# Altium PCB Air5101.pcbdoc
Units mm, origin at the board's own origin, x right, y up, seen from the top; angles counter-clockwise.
Board outline 69.1 x 28.3 mm, 2 copper layers (Top Layer, Bottom Layer); 1 components, 0 nets, 10 pads, 0 vias.
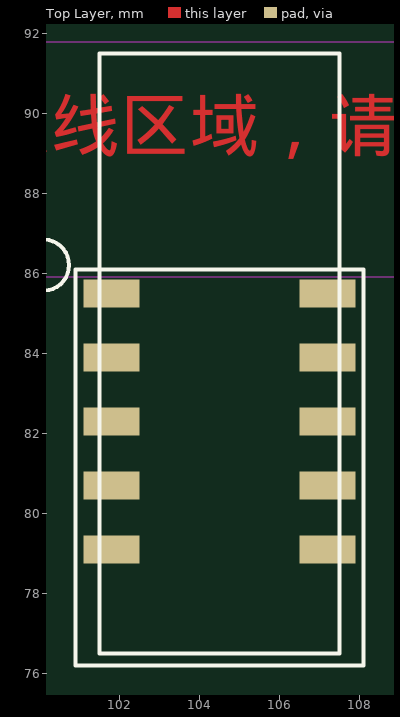
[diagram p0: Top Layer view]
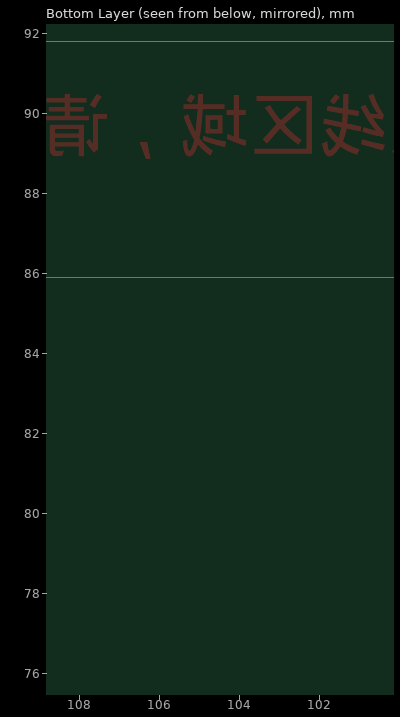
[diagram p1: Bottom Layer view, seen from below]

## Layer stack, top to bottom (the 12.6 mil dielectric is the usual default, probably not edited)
Top Layer: signal copper (thickness not stored)
Dielectric: dielectric 0.32, FR-4, Dk 4.8
Bottom Layer: signal copper (thickness not stored)

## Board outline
138.95,69.85 69.85,69.85 69.85,98.15 138.95,98.15

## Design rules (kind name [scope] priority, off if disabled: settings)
BoardOutlineClearance safeClearance [All] p0: genericclearance=0.254 ignorepadtopadclearanceinfootprint=FALSE except(0: Arc-SplitContinuation Track-SplitContinuation SMDPad-SplitContinuation THPad-SplitContinuation Via-SplitContinuation Fill-SplitContinuation Poly-SplitContinuation Region-SplitContinuation Text-SplitContinuation; 0.152: Track-CutoutEdge SMDPad-CutoutEdge THPad-CutoutEdge Via-CutoutEdge Fill-CutoutEdge Region-CutoutEdge; 0.3: Track-OutlineEdge SMDPad-OutlineEdge THPad-OutlineEdge Via-OutlineEdge Fill-OutlineEdge Region-OutlineEdge Poly-OutlineEdge Text-OutlineEdge)
Clearance safeClearance [All] p1: gap=0.178 ignorepadtopadclearanceinfootprint=FALSE except(0.152: Track-Track Track-SMDPad SMDPad-SMDPad Track-THPad SMDPad-THPad THPad-THPad Track-Via SMDPad-Via THPad-Via Via-Via Track-Fill SMDPad-Fill THPad-Fill Via-Fill Fill-Fill Track-Region SMDPad-Region THPad-Region Via-Region Fill-Region Region-Region Track-Poly SMDPad-Poly THPad-Poly Via-Poly Fill-Poly Region-Poly Poly-Poly Track-Text SMDPad-Text THPad-Text Via-Text Fill-Text Region-Text Poly-Text Text-Text; 0.175: Track-Hole SMDPad-Hole THPad-Hole Via-Hole Fill-Hole Region-Hole Poly-Hole Text-Hole Sheet-Hole; 0.3: Track-Sheet SMDPad-Sheet THPad-Sheet Via-Sheet Fill-Sheet Region-Sheet Poly-Sheet Text-Sheet)
DiffPairsRouting differentialPair [All] p1: maxuncoupledlength=10 minlimit=6 maxlimit=6 mostfreqgap=6 toplayer_minwidth=5 toplayer_prefwidth=10 toplayer_maxwidth=100 bottomlayer_minwidth=5 bottomlayer_prefwidth=10 bottomlayer_maxwidth=100
PasteMaskExpansion pasteMaskExpansion [All] p1: expansion=0
PlaneConnect innerPlane [All] p1: planeconnectstyle=Relief reliefexpansion=0.508 reliefentries=4 reliefconductorwidth=0.254 reliefairgap=0.254
PolygonConnect copperRegion [All] p1: connectstyle=Relief reliefentries=4 reliefconductorwidth=10 polygonreliefangle="90 Angle" airgapwidth=10
RoutingVias viaSize [All] p1: viastyle="Through Hole" holewidth=12.0078 minholewidth=11.811 maxholewidth=236.2204 width=24.0158 minwidth=19.685 maxwidth=393.7008
SolderMaskExpansion solderMaskExpansion [All] p1: useseparateexpansions=TRUE expansion=2 expansionbottom=2
Width trackWidth [All] p1: maxlimit=100 minlimit=5 preferedwidth=10

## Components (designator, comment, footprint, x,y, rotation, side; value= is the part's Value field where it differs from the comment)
? "AIR5101" AIR5101 104.5,84 r0 top

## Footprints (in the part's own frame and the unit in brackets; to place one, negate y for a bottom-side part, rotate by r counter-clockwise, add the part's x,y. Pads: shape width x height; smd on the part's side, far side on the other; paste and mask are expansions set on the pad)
AIR5101 [mm]
  rect 1.4x0.7 smd: 1(-2.7,1.5) 2(-2.7,-0.1) 3(-2.7,-1.7) 4(-2.7,-3.3) 5(-2.7,-4.9) 6(2.7,-4.9) 7(2.7,-3.3) 8(2.7,-1.7) 9(2.7,-0.1) 10(2.7,1.5)
  Board Outline Layer region: -28.3,7.8 28.1,7.8 28.1,1.9 -28.3,1.9
  silkscreen extent -5.04,-7.8 3.6,7.5

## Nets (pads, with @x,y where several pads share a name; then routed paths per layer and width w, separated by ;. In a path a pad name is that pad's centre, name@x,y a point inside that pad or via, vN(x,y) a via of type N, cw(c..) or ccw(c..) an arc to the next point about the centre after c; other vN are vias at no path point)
pads on no net: ?.1 ?.2 ?.3 ?.4 ?.5 ?.6 ?.7 ?.8 ?.9 ?.10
